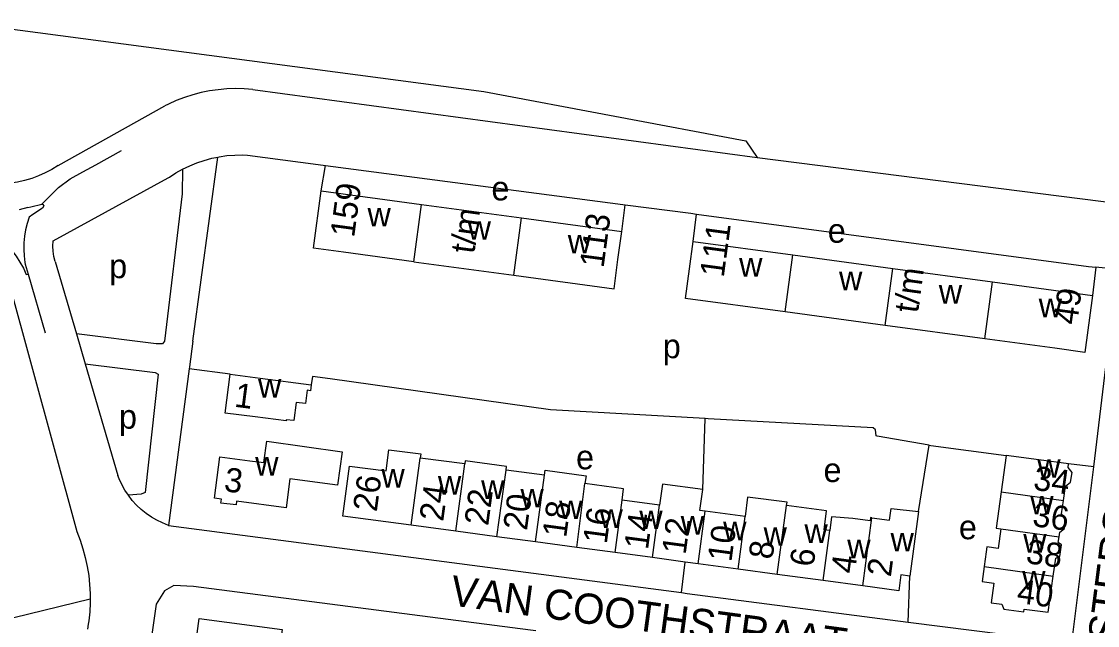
# Model space of a CAD drawing. Extents: x 161258 to 163262, y 380749 to 382054.
# Drawn here: x 161562.6 to 161740.8, y 381583.2 to 381683.2 of the extents above; entities that cross this region are included whole.
import ezdxf

# ---------------------------------------------------------------- set-up
doc = ezdxf.new("R2010")
doc.units = 0
for name, color, linetype in [('BLT_Basislijn', 7, 'Continuous'), ('BLT_Bebouwing', 7, 'Continuous'), ('BLT_Centroide', 7, 'Continuous'), ('BLT_Huisnummer', 7, 'Continuous'), ('BLT_Huisnummer_ tussenligend', 7, 'Continuous'), ('BLT_Huisnummer_reeks', 7, 'Continuous'), ('BLT_Onderverdeling_panden', 7, 'Continuous'), ('BLT_Straatnaam', 7, 'Continuous')]:
    doc.layers.add(name, color=color, linetype=linetype)

msp = doc.modelspace()

# ---------------------------------------------------------------- linework, layer by layer
at = {"layer": 'BLT_Basislijn'}
for p, q in [((161551.26, 381683.18), (161639.13, 381671.6)), ((161600.88, 381671.93), (161684.41, 381660.64)), ((161568.62, 381659.32), (161586.33, 381669.21)), ((161590.97, 381630.24), (161595.1, 381660.74)), ((161612.21, 381655.12), (161612.91, 381659.35)), ((161684.41, 381660.64), (161757.09, 381651.44)), ((161563.59, 381652.36), (161562.2, 381651.98)), ((161662, 381648.42), (161662.55, 381652.85)), ((161673.82, 381646.78), (161674.36, 381651.3)), ((161563.15, 381643.02), (161563.64, 381641.36)), ((161568.14, 381643.45), (161571.65, 381631.46)), ((161563.35, 381641.28), (161563.64, 381641.36)), ((161563.64, 381641.36), (161566.46, 381631.65)), ((161740.52, 381642.49), (161739.98, 381637.83)), ((161740.2, 381609.45), (161744.14, 381642.12)), ((161744.14, 381642.12), (161740.52, 381642.49)), ((161560.44, 381639.98), (161571.71, 381598.71)), ((161571.65, 381631.46), (161573.11, 381626.47)), ((161573.11, 381626.47), (161578.54, 381607.99)), ((161590.35, 381625.67), (161586.92, 381599.75)), ((161597.15, 381624.77), (161590.35, 381625.67)), ((161675.41, 381605.68), (161675.81, 381617.43)), ((161711.19, 381602.05), (161712.94, 381613.04)), ((161740.2, 381609.45), (161736.04, 381609.92)), ((161586.92, 381599.75), (161671.9, 381588.61)), ((161671.9, 381588.61), (161672.48, 381593.68)), ((161709.43, 381583.72), (161709.75, 381591.35)), ((161573.62, 381583.36), (161573.5, 381582.58))]:
    msp.add_line(p, q, dxfattribs=at)
for points in [[(161600.88, 381671.93), (161599.44, 381672.04), (161598.01, 381672.07), (161596.57, 381672.02), (161595.14, 381671.89), (161593.71, 381671.68), (161592.31, 381671.4), (161590.92, 381671.04), (161589.55, 381670.59), (161588.21, 381670.08), (161586.9, 381669.49), (161586.33, 381669.21)], [(161639.13, 381671.6), (161682.56, 381663.41), (161684.41, 381660.64)], [(161565.95, 381652.95), (161567.25, 381654.27), (161568.68, 381655.71), (161570.62, 381657.11), (161572.74, 381658.28), (161574.86, 381659.45), (161579.15, 381661.83)], [(161589.25, 381658.72), (161590.42, 381659.29), (161591.61, 381659.78), (161592.83, 381660.19), (161594.07, 381660.53), (161595.1, 381660.74)], [(161595.1, 381660.74), (161595.32, 381660.79), (161596.6, 381660.97), (161597.88, 381661.07), (161599.16, 381661.09), (161599.98, 381661.06)], [(161599.98, 381661.06), (161611.7, 381659.51), (161612.91, 381659.35)], [(161568.62, 381659.32), (161567.58, 381658.68), (161566.5, 381658.11), (161565.39, 381657.62), (161564.25, 381657.2), (161563.08, 381656.85), (161561.89, 381656.59), (161560.69, 381656.4), (161559.48, 381656.29), (161558.26, 381656.26), (161557.45, 381656.28)], [(161612.91, 381659.35), (161661.37, 381653.01), (161662.55, 381652.85)], [(161567.8, 381646.89), (161586.83, 381657.28), (161587.07, 381657.4)], [(161589.25, 381658.72), (161589.16, 381654.66), (161586.23, 381630.27), (161585.91, 381629.83), (161584.89, 381629.81), (161571.65, 381631.46)], [(161587.07, 381657.4), (161588.15, 381658.1), (161589.25, 381658.72)], [(161566.02, 381652.28), (161564.42, 381651.22), (161563.84, 381650.78), (161563.5, 381649.75), (161563.24, 381648.69), (161563.05, 381647.62), (161562.95, 381646.53), (161562.92, 381645.44), (161562.98, 381644.36), (161563.11, 381643.27), (161563.15, 381643.02)], [(161563.59, 381652.36), (161564.09, 381652.5), (161565.95, 381652.95)], [(161565.95, 381652.95), (161566.1, 381652.87), (161566.24, 381652.64), (161566.02, 381652.28)], [(161662.55, 381652.85), (161673.42, 381651.43), (161674.36, 381651.3)], [(161551.1, 381651.44), (161552.24, 381651.14), (161553.37, 381650.77), (161554.46, 381650.32), (161555.52, 381649.8), (161556.55, 381649.2), (161557.53, 381648.54), (161558.46, 381647.82), (161559.35, 381647.03), (161560.18, 381646.18), (161560.95, 381645.29), (161561.65, 381644.34), (161562.3, 381643.34), (161562.87, 381642.31), (161563.35, 381641.28)], [(161674.36, 381651.3), (161739.35, 381642.61), (161740.52, 381642.49)], [(161568.14, 381643.45), (161567.93, 381644.28), (161567.81, 381645.13), (161567.76, 381645.98), (161567.8, 381646.89)], [(161590.97, 381630.24), (161590.39, 381625.99), (161590.35, 381625.67)], [(161573.11, 381626.47), (161584.7, 381625.07), (161585.18, 381624.79), (161583.04, 381605.17), (161582.39, 381604.94), (161580.28, 381604.73)], [(161675.81, 381617.43), (161650.17, 381618.89), (161613.68, 381624), (161610.75, 381624.41), (161610.56, 381623.04)], [(161712.94, 381613.04), (161704.33, 381614.51), (161704.14, 381614.58), (161704.06, 381615.54), (161703.68, 381615.91), (161676.29, 381617.4), (161675.81, 381617.43)], [(161712.94, 381613.04), (161713.2, 381613), (161725.71, 381611.33)], [(161709.43, 381583.72), (161736.54, 381580.27), (161740.2, 381609.45)], [(161580.28, 381604.73), (161579.7, 381605.6), (161579.18, 381606.52), (161578.74, 381607.47), (161578.54, 381607.99)], [(161586.92, 381599.75), (161585.94, 381600.14), (161584.99, 381600.6), (161584.08, 381601.13), (161583.22, 381601.73), (161582.4, 381602.39), (161581.63, 381603.11), (161580.92, 381603.89), (161580.28, 381604.73)], [(161571.71, 381598.71), (161572.26, 381597.31), (161572.73, 381595.88), (161573.13, 381594.42), (161573.45, 381592.94), (161573.69, 381591.46), (161573.85, 381589.95), (161573.93, 381588.45), (161573.93, 381587.52)], [(161647.76, 381582.3), (161646.86, 381582.41), (161591.08, 381589.63), (161587.77, 381589.77), (161586.23, 381588.91), (161584.89, 381586.68), (161583.08, 381574.39), (161573.92, 381500), (161570.58, 381468.89), (161570.42, 381465.8), (161572.24, 381462.03), (161574.18, 381460.03), (161576.58, 381458.66), (161578.81, 381458.22), (161583.37, 381458.7), (161593.26, 381463), (161639.49, 381480.37)], [(161671.9, 381588.61), (161672.86, 381588.48), (161709.43, 381583.72)], [(161573.93, 381587.52), (161528.25, 381576.35), (161521.11, 381573.74), (161515.34, 381571.29), (161514.83, 381571.14)], [(161573.93, 381587.52), (161573.93, 381586.94), (161573.86, 381585.43), (161573.7, 381583.93), (161573.62, 381583.36)]]:
    msp.add_lwpolyline(points, dxfattribs=at)
at = {"layer": 'BLT_Bebouwing'}
for p, q in [((161612.21, 381655.12), (161628.81, 381652.89)), ((161628.81, 381652.89), (161645.41, 381650.66)), ((161645.41, 381650.66), (161662, 381648.42)), ((161673.82, 381646.78), (161690.36, 381644.55)), ((161627.53, 381643.4), (161644.13, 381641.16)), ((161690.36, 381644.55), (161706.9, 381642.28)), ((161706.9, 381642.28), (161723.44, 381640.05)), ((161723.44, 381640.05), (161739.98, 381637.83)), ((161705.63, 381632.86), (161689.09, 381635.08)), ((161722.17, 381630.63), (161705.63, 381632.86)), ((161636, 381609.91), (161628.59, 381610.86)), ((161725.71, 381611.33), (161724.88, 381605.3)), ((161649.19, 381608.05), (161642.83, 381608.9)), ((161668.26, 381603.1), (161662.06, 381603.93)), ((161682.42, 381601.19), (161675.82, 381602.08)), ((161629.96, 381599.39), (161627.1, 381599.77)), ((161634.51, 381598.78), (161629.96, 381599.39)), ((161641.33, 381597.86), (161634.51, 381598.78)), ((161647.7, 381597.01), (161641.33, 381597.86)), ((161654.57, 381596.09), (161647.7, 381597.01)), ((161660.89, 381595.24), (161654.57, 381596.09)), ((161667.09, 381594.4), (161660.89, 381595.24)), ((161672.48, 381593.68), (161667.09, 381594.4)), ((161674.65, 381593.39), (161672.48, 381593.68)), ((161681.26, 381592.5), (161674.65, 381593.39)), ((161687.77, 381591.62), (161681.26, 381592.5)), ((161695.35, 381590.61), (161687.77, 381591.62))]:
    msp.add_line(p, q, dxfattribs=at)
for points in [[(161627.53, 381643.4), (161615.89, 381644.97), (161610.94, 381645.63), (161612.21, 381655.12)], [(161644.13, 381641.16), (161660.72, 381638.93), (161661.37, 381643.77), (161662, 381648.42)], [(161689.09, 381635.08), (161672.55, 381637.31), (161673.21, 381642.24), (161673.82, 381646.78)], [(161739.98, 381637.83), (161738.71, 381628.4), (161733.75, 381629.07), (161722.17, 381630.63)], [(161608.06, 381620.11), (161607.65, 381617.09), (161606.43, 381617.25), (161606.4, 381617.05), (161601.28, 381617.71), (161596.32, 381618.35), (161597.15, 381624.77)], [(161597.15, 381624.77), (161602.11, 381624.13), (161610.56, 381623.04)], [(161610.56, 381623.04), (161610.43, 381622.04), (161609.89, 381622.12), (161609.59, 381619.9), (161608.06, 381620.11)], [(161602.73, 381610.15), (161603.18, 381613.69), (161615.69, 381611.93), (161614.92, 381606.43), (161607, 381607.46), (161606.38, 381602.67), (161598.19, 381603.73), (161598.11, 381603.13), (161595.58, 381603.45), (161595.67, 381604.09), (161594.52, 381604.24), (161595.41, 381611.1), (161600.36, 381610.46), (161602.73, 381610.15)], [(161627.1, 381599.77), (161615.78, 381601.29), (161616.45, 381606.25), (161616.9, 381609.57), (161622.99, 381608.79), (161623.44, 381612.26), (161628.69, 381611.59), (161628.59, 381610.86)], [(161736.04, 381609.92), (161731.08, 381610.6), (161725.71, 381611.33)], [(161642.83, 381608.9), (161642.92, 381609.5), (161636.07, 381610.42), (161636, 381609.91)], [(161735.18, 381603.89), (161735.5, 381606.22), (161736.37, 381606.88), (161736.6, 381608.5), (161735.96, 381609.34), (161736.04, 381609.92)], [(161649.19, 381608.05), (161649.31, 381608.89), (161656.1, 381607.97), (161655.89, 381606.66)], [(161662.06, 381603.93), (161662.31, 381605.8), (161655.89, 381606.66)], [(161675.41, 381605.68), (161668.73, 381606.58), (161668.26, 381603.1)], [(161675.82, 381602.08), (161674.94, 381602.2), (161675.41, 381605.68)], [(161689.3, 381603.03), (161689.38, 381603.57), (161682.86, 381604.44), (161682.42, 381601.19)], [(161724.88, 381605.3), (161724.05, 381599.27), (161724.83, 381599.17)], [(161734.44, 381597.85), (161734.55, 381598.61), (161735.35, 381599.22), (161735.57, 381600.78), (161734.88, 381601.68), (161735.18, 381603.89)], [(161696.47, 381598.9), (161695.51, 381599.03), (161695.93, 381602.14), (161689.3, 381603.03)], [(161703.44, 381601), (161706.37, 381600.59), (161706.65, 381602.52), (161711.19, 381602.05)], [(161711.19, 381602.05), (161709.75, 381591.35)], [(161703.44, 381601), (161703.19, 381601.03), (161703.17, 381600.48), (161700.26, 381600.87), (161696.77, 381601.18), (161696.47, 381598.9)], [(161724.83, 381599.17), (161724.38, 381595.94), (161722.5, 381596.2), (161722.39, 381595.39), (161722.05, 381592.91)], [(161733.48, 381591.34), (161733.89, 381594.32), (161734.57, 381594.6), (161734.83, 381596.53), (161734.32, 381596.93), (161734.44, 381597.85)], [(161709.75, 381591.35), (161708.26, 381591.55), (161707.9, 381588.92), (161701.92, 381589.72)], [(161722.05, 381592.91), (161721.71, 381590.44), (161723.65, 381590.17), (161723.2, 381586.93), (161724.99, 381586.68), (161725.32, 381585.86), (161728.62, 381585.41), (161728.69, 381585.89), (161732.66, 381585.35), (161733.48, 381591.34)], [(161701.92, 381589.72), (161695.35, 381590.61)], [(161591.06, 381577.29), (161592, 381584.35), (161605.75, 381582.53), (161604.81, 381575.47)]]:
    msp.add_lwpolyline(points, dxfattribs=at)
at = {"layer": 'BLT_Onderverdeling_panden'}
for p, q in [((161627.53, 381643.4), (161628.81, 381652.89)), ((161644.13, 381641.16), (161645.41, 381650.66)), ((161689.09, 381635.08), (161690.36, 381644.55)), ((161705.63, 381632.86), (161706.9, 381642.28)), ((161722.17, 381630.63), (161723.44, 381640.05)), ((161627.1, 381599.77), (161628.59, 381610.86)), ((161634.51, 381598.78), (161636, 381609.91)), ((161641.33, 381597.86), (161642.83, 381608.9)), ((161647.7, 381597.01), (161649.19, 381608.05)), ((161654.57, 381596.09), (161655.89, 381606.66)), ((161660.89, 381595.24), (161662.06, 381603.93)), ((161724.88, 381605.3), (161735.18, 381603.89)), ((161667.09, 381594.4), (161668.26, 381603.1)), ((161674.65, 381593.39), (161675.82, 381602.08)), ((161687.77, 381591.62), (161689.3, 381603.03)), ((161681.26, 381592.5), (161682.42, 381601.19)), ((161701.92, 381589.72), (161703.44, 381601)), ((161695.35, 381590.61), (161696.47, 381598.9)), ((161724.83, 381599.17), (161734.44, 381597.85)), ((161722.05, 381592.91), (161733.48, 381591.34))]:
    msp.add_line(p, q, dxfattribs=at)

# ---------------------------------------------------------------- texts
at = {"layer": 'BLT_Centroide'}
for s, p in [('e', (161640.41, 381653.56)), ('w', (161619.88, 381649.25)), ('w', (161636.47, 381647.03)), ('e', (161696.13, 381646.55)), ('w', (161653.06, 381644.78)), ('p', (161577.09, 381640.68)), ('w', (161681.45, 381640.94)), ('w', (161698, 381638.69)), ('w', (161714.53, 381636.47)), ('w', (161731.08, 381634.22)), ('p', (161668.8, 381627.43)), ('w', (161601.75, 381620.91)), ('p', (161578.71, 381615.76)), ('w', (161601.27, 381608)), ('e', (161654.43, 381609.03)), ('w', (161622.18, 381606)), ('e', (161695.43, 381606.92)), ('w', (161730.84, 381607.62)), ('w', (161631.55, 381604.83)), ('w', (161638.7, 381604.14)), ('w', (161645.22, 381602.72)), ('w', (161651.62, 381600.78)), ('w', (161729.67, 381601.56)), ('w', (161658.31, 381599.31)), ('w', (161664.91, 381599.12)), ('w', (161671.78, 381598.2)), ('w', (161678.8, 381597.27)), ('e', (161717.86, 381597.45)), ('w', (161685.5, 381596.36)), ('w', (161692.27, 381596.83)), ('w', (161706.53, 381595.42)), ('w', (161699.36, 381594.28)), ('w', (161728.52, 381595.25)), ('w', (161728.34, 381589.12))]:
    msp.add_text(s, height=4, dxfattribs=at).set_placement(p)
at = {"layer": 'BLT_Huisnummer'}
for s, rotation, p in [('1', 352.6234, (161597.7, 381619.41)), ('3', 352.6249, (161595.99, 381605.42)), ('34', 352.1847, (161730.05, 381605.66)), ('26', 82.3463, (161621.41, 381601.89)), ('22', 82.3502, (161639.87, 381599.58)), ('18', 82.3513, (161652.79, 381597.61)), ('14', 82.3505, (161666.34, 381595.61)), ('10', 82.3488, (161680.16, 381593.59)), ('6', 82.3507, (161693.77, 381592.76)), ('2', 82.3463, (161706.57, 381591.1)), ('40', 352.1769, (161727.32, 381586.94))]:
    msp.add_text(s, height=4, rotation=rotation, dxfattribs=at).set_placement(p)
at = {"layer": 'BLT_Huisnummer_ tussenligend'}
for s, rotation, p in [('24', 82.3502, (161632.42, 381600.29)), ('20', 82.3513, (161646.29, 381598.79)), ('16', 82.3505, (161659.51, 381596.56)), ('36', 352.1847, (161729.91, 381599.65)), ('12', 82.3488, (161672.58, 381594.8)), ('8', 82.3507, (161686.96, 381593.99)), ('38', 352.1847, (161728.83, 381593.51)), ('4', 82.3463, (161700.61, 381591.64))]:
    msp.add_text(s, height=4, rotation=rotation, dxfattribs=at).set_placement(p)
at = {"layer": 'BLT_Huisnummer_reeks'}
for s, rotation, p in [('159', 82.3326, (161617.66, 381647.31)), ('t/m', 82.2136, (161637.56, 381644.63)), ('113', 82.3247, (161658.98, 381642.28)), ('111', 82.3305, (161678.89, 381640.7)), ('t/m', 82.2136, (161711.07, 381634.8)), ('49', 82.3264, (161737.43, 381632.85))]:
    msp.add_text(s, height=4, rotation=rotation, dxfattribs=at).set_placement(p)
at = {"layer": 'BLT_Straatnaam'}
for s, rotation, p in [('JOHAN VESTERSSTRAAT', 82.7626, (161739.95, 381547.04)), ('VAN COOTHSTRAAT', 352.3352, (161633.39, 381586.54))]:
    msp.add_text(s, height=5, rotation=rotation, dxfattribs=at).set_placement(p)

doc.saveas('drawing.dxf')
